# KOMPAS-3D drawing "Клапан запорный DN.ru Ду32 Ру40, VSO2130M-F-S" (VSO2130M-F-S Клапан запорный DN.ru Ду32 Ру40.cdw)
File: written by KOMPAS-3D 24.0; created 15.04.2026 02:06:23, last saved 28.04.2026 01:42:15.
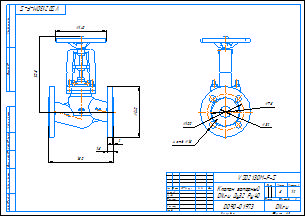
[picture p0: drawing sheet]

Document properties: Автор: DN.ru; Форматы листов документа: A3; Полное имя файла: VSO2130M-F-S Клапан запорный DN.ru Ду32 Ру40.m3d; Масса: 8; Наименование: Клапан запорный DN.ru Ду32 Ру40; Количество листов документа: 1; Примечание: D090-01973

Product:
- Part/product: Клапан запорный DN.ru Ду32 Ру40  | designation VSO2130M-F-S
    Масса: 8
    Раздел спецификации: Прочие изделия
    Примечание: D090-01973

Views: Вид 1, Вид:1, Проекционный вид 2
Referenced files in C:\Работа\VSO2130M-F-S Клапан запорный DN.ru\DN20\: VSO2130M-F-S DN20 PN40  Клапан запорный сильфонный DN.ru.m3d
Referenced files in C:\Работа\VSO2130M-F-S Клапан запорный DN.ru\DN32\: VSO2130M-F-S Клапан запорный DN.ru Ду32 Ру40.m3d
Referenced files in C:\Program Files\ASCON\KOMPAS-3D v24\Templates\: Чертеж_DN.ru.cdt
Referenced files in C:\Работа\ГОТОВЫЕ ИСХОДНИКИ\VSO2130M-F-S Клапан запорный сильфонный DN.ru Ду15-100 Ру40\DN32\: VSO2130M-F-S Клапан запорный DN.ru Ду32 Ру40.m3d
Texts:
  VSO2130M-F-S
  Чертеж_DN.ru.cdt
  Клапан запорный
  DN.ru Ду32 Ру40
  Клапан запорный DN.ru Ду32 Ру40
  VSO2130M-F-S  Клапан запорный DN.ru Ду32 Ру40
Dimensions and other numbers on the sheet: 0; 3; 2; 4; 140; 18; 208; 180; 1; 5; 32; 78; 100; 4 отв.; 1:2; 8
